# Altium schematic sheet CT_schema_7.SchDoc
size 147 x 119 mm
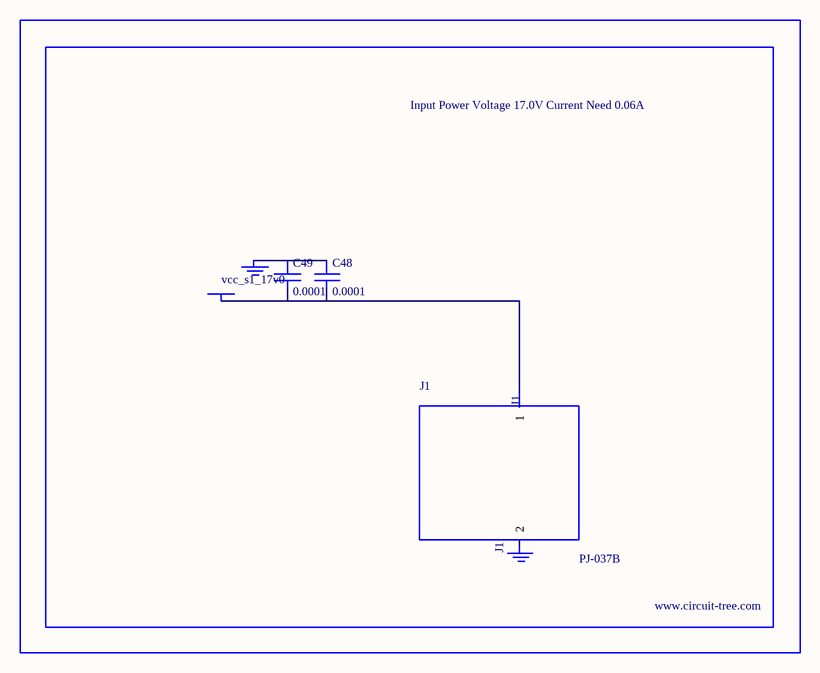
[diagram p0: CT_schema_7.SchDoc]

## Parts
BORDER6  (no value)
C48  0.0001  [EXV-9H]
C49  0.0001  [EXV-9H]
GND_INSTANCE_6_0  (no value)
GND_INSTANCE_6_1  (no value)
J1  PJ-037B  [PJ-037B_PACKAGE]
POWER_INSTANCE_6_0  vcc_s1_17v0

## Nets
NetC48_1: C48.1 C49.1 GND_INSTANCE_6_0.0(GND)
NetC48_2: C48.2 C49.2 J1.1 POWER_INSTANCE_6_0.0(PWR)

Not connected (* = marked no-connect by the designer): GND_INSTANCE_6_1 0(GND); J1 2

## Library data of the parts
BORDER6 = BORDER_PAGE6
C48 C49 = EDK107M035A9HAA
GND_INSTANCE_6_0 GND_INSTANCE_6_1 = GND
POWER_INSTANCE_6_0 = PWR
